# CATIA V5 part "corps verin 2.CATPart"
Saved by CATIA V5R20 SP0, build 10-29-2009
Part number: corps verin 2
Bounding box of the stored display mesh (mm): x -100 to 100, y -215 to -155, z 16 to 41
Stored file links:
  D:\Dropbox\Pack 1 sylvain\mmoreau\mmoreau\mmoreau\fin\corps verin 2.CATPart
  U:\think motion\fin\think motion2.CATProduct
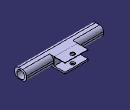
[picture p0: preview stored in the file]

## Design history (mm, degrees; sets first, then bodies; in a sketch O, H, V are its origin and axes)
Set1
  Plane1: linked copy from another document
  Plane2: linked copy from another document
  Line1: linked copy from another document
Body1 (main body)
  Sketch1 on Plane1, origin (0, -205, 0), H (-1, 0, 0), V (0, 0, 1)
    line L1 (100, 41) -> (-100, 41)
    line L2 (-100, 41) -> (-100, 16)
    line L3 (-100, 16) -> (100, 16)
    line L4 (100, 16) -> (100, 41)
    distance L4 L2 = 200
    distance L3 L1 = 25
    distance H L3 = 16
    horizontal: L1 H, L3 H
    vertical: L2 V, L4 V
    symmetry: L4 L2 V
  Pad1: profile Sketch1, direction (0, 1, 0), length 20, opposite side length 10
  Sketch2 on face of Pad1 from Sketch1.L4, origin (-100, 0, 0), H (0, -1, 0), V (0, 0, 1)
    circle A1 centre (200, 27) radius 10
    point P1 (200, 27)
    reference projected point E1 (200, 30) from Line1
    reference projected point E2 (200, 30) from Line1
    distance P1 E1 H = 0
    distance P1 E2 = 3
    radius A1 = 10
  Pocket1: profile Sketch2, direction (1, 0, 0), length 210
  Sketch3 on end face of Pad1, origin (0, -185, 0), H (-1, 0, 0), V (0, 0, 1)
    line L1 (-30, 41) -> (30, 41)
    line L2 (30, 41) -> (30, 16)
    line L3 (30, 16) -> (-30, 16)
    line L4 (-30, 16) -> (-30, 41)
    reference intersected line E1 (-100, 41) -> (100, 41) from face of Pad1 from Sketch1.L1
    distance L2 L4 = 60
    distance L1 L3 = 25
    distance L1 E1 = 0
    horizontal: L1 H, L3 H
    vertical: L2 V, L4 V
    symmetry: L2 L4 V
  Pad2: profile Sketch3, direction (0, 1, 0), length 30
  Sketch4 on face of Pad2, origin (5.4386, -179.0375, 41), H (1, 0, 0), V (0, 1, 0)
    point P1 (-5.4386, 14.0375)
    reference intersected line E1 (94.5614, -35.9625) -> (-105.4386, -35.9625) from start face of Pad1
    reference intersected line E2 (-35.4386, -5.9625) -> (-35.4386, 24.0375) from face of Pad2 from Sketch3.L2
    distance P1 E1 = 50
    distance P1 E2 = 30
  Hole1: placed by Sketch4, at (0, -165, 41) direction (0, 0, -1), diameter 10, through (limit type 3)
  Sketch5 on end face of Pad2, origin (0, -155, 0), H (-1, 0, 0), V (0, 0, 1)
    line L1 (-30, 40) -> (30, 40)
    line L2 (30, 40) -> (30, 20)
    line L3 (30, 20) -> (-30, 20)
    line L4 (-30, 20) -> (-30, 40)
    reference intersected line E1 through (0, 41) direction (1, 0) from face of Pad2
    reference intersected line E2 through (0, 16) direction (-1, 0) from face of Pad2
    distance L4 L2 = 60
    distance L1 E1 = 1
    distance L3 E2 = 4
    horizontal: L1 H, L3 H
    vertical: L2 V, L4 V
    symmetry: L4 L2 V
  Pocket2: profile Sketch5, direction (0, -1, 0), length 28
  Fillet1: radius 10, on edge [start face of Pad1 | face of Pad2] (x2); edge [face of Pad2 | end face of Pad1] (x4)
